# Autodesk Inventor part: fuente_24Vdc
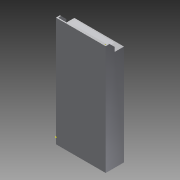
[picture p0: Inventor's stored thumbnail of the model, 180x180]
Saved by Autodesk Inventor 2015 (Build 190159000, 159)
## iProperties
Created: 2016-06
Part Number: fuente_24Vdc
Material: Genérico
Document SubType Name: Modeling
Designer: Diego
Density: 1 g/cm^3
Appearance: Valor por defecto
Author: Diego
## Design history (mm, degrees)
sketch "Boceto1"
  geometry: 1 further point
sketch "Boceto2"
  geometry: L1 (0, 0)-(95, 0); L2 (95, 0)-(95, 35); L3 (95, 35)-(0, 35); L4 (0, 35)-(0, 0)
  constraints: 8 end point, 2 parallel, 1 horizontal, 1 perpendicular
  dimensions: "d0" = 95 distance of L3.end L2.end; "d1" = 35 distance of L2.end L1.end
extrude "Extrusión1" new body sketch "Boceto2" distance "d2" = 180; taper "d3" = 0 deg
sketch "Boceto3"
  geometry: L1 (0, 35)-(0, 0) reference; L2 (0, 17.5)-(0, 0); L3 (0, 0)-(95, 0); L4 (95, 0)-(95, 17.5); L5 (95, 0)-(95, 35) reference; L6 (93, 17.5)-(93, 2); L7 (93, 2)-(2, 2); L8 (2, 2)-(2, 17.5); L9 (0, 17.5)-(2, 17.5); L10 (93, 17.5)-(95, 17.5)
  constraints: 16 end point, 2 collinear, 2 midpoint, 2 perpendicular, 1 horizontal, 2 other
  dimensions: "d4" = 2 distance between parallel lines of L3 L7
extrude "Extrusión2" join sketch "Boceto3" distance "d5" = 18; taper "d6" = 0 deg
chamfer "Chaflán1" distance "d7" = 10; stored, may be unused: second distance "d8" = 2, angle "d9" = 45 deg
chamfer "Chaflán2" distance "d10" = 10; stored, may be unused: second distance "d11" = 2, angle "d12" = 45 deg
sketch "Boceto4"
  geometry: L1 (93, 0)-(-2, 0) reference; L2 (2.896, 0)-(77.896, 0); L3 (77.896, 0)-(77.896, -10); L4 (77.896, -10)-(2.896, -10); L5 (2.896, -10)-(2.896, 0); 1 further point
  constraints: 8 end point, 2 parallel, 1 horizontal, 1 perpendicular, 1 point on line
  dimensions: "d13" = 75 distance of L3.end L4.end; "d14" = 10 distance of L2.end L3.end
extrude "Extrusión3" join sketch "Boceto4" distance "d15" = 1; taper "d16" = 0 deg
sketch "Boceto5" dims "d23" = 10
  geometry: L1 (77.896, -10)-(2.896, -10) reference; L2 (2.896, 0)-(4.396, 0); L3 (4.396, 0)-(4.396, -10); L4 (4.396, -10)-(2.896, -10); L5 (2.896, -10)-(2.896, 0); L6 (14.846, 0)-(14.846, -10); L7 (13.346, -10)-(13.346, 0); L8 (13.346, 0)-(14.846, 0); L9 (14.846, -10)-(13.346, -10); L10 (25.296, 0)-(25.296, -10); L11 (23.796, -10)-(23.796, 0); L12 (23.796, 0)-(25.296, 0); L13 (25.296, -10)-(23.796, -10); L14 (35.746, 0)-(35.746, -10); L15 (34.246, -10)-(34.246, 0); L16 (34.246, 0)-(35.746, 0); L17 (35.746, -10)-(34.246, -10); L18 (46.196, 0)-(46.196, -10); L19 (44.696, -10)-(44.696, 0); L20 (44.696, 0)-(46.196, 0); L21 (46.196, -10)-(44.696, -10); L22 (56.646, 0)-(56.646, -10); L23 (55.146, -10)-(55.146, 0); L24 (55.146, 0)-(56.646, 0); L25 (56.646, -10)-(55.146, -10); L26 (67.096, 0)-(67.096, -10); L27 (65.596, -10)-(65.596, 0); L28 (65.596, 0)-(67.096, 0); L29 (67.096, -10)-(65.596, -10); L30 (77.546, 0)-(77.546, -10); L31 (76.046, -10)-(76.046, 0); L32 (76.046, 0)-(77.546, 0); L33 (77.546, -10)-(76.046, -10); 1 further point
  constraints: 64 end point, 2 horizontal, 2 parallel, 1 perpendicular, 1 point on line, 56 other
  dimensions: "d17" = 1.5 distance of L3.end L4.end; "d20" = 10.45 distance of L2.end L6.start
extrude "Extrusión4" join sketch "Boceto5" distance "d25" = 10; taper "d26" = 0 deg
chamfer "Chaflán3" distance "d27" = 6; stored, may be unused: second distance "d28" = 2, angle "d29" = 45 deg
chamfer "Chaflán4" distance "d30" = 6; stored, may be unused: second distance "d31" = 2, angle "d32" = 45 deg
chamfer "Chaflán5" distance "d33" = 6; stored, may be unused: second distance "d34" = 2, angle "d35" = 45 deg
chamfer "Chaflán6" distance "d36" = 6; stored, may be unused: second distance "d37" = 2, angle "d38" = 45 deg
chamfer "Chaflán7" distance "d39" = 6; stored, may be unused: second distance "d40" = 2, angle "d41" = 45 deg
sketch "Boceto6"
  geometry: L1 (-95, 35)-(0, 35) reference; L2 (0, 0)-(-95, 0) reference; L3 (0, 35)-(0, 0) reference; L4 (-95, 35)-(0, 35) reference; L5 (-95, 0)-(-95, 35) reference; L6 (0, 35)-(-95, 35); L7 (-95, 35)-(-95, 0); L8 (-95, 0)-(0, 0); L9 (0, 0)-(0, 35); L10 (-2, 2)-(-93, 2); L11 (-93, 2)-(-93, 33); L12 (-93, 33)-(-2, 33); L13 (-2, 33)-(-2, 2); 1 further point
  constraints: 16 end point, 2 parallel, 1 horizontal, 1 perpendicular, 3 other
  dimensions: "d42" = 2 distance between parallel lines of L3 L13
extrude "Extrusión5" cut sketch "Boceto6" distance "d43" = 178; taper "d44" = 0 deg
sketch "Boceto7"
  geometry: L1 (5, -180)-(5, -175); L2 (5, -175)-(0, -175); 631 further points
  constraints: 4 end point, 1 coincident, 1 horizontal, 1 vertical, 629 other
  dimensions: "d45" = 5 distance of L2.end L1.end; "d46" = 5 distance of L1.end L1.start; "d49" = 5 distance of point (5, -175) point (5, -170); "d52" = 5 distance of point (5, -175) point (10, -175)
hole "Agujero1" sketch "Boceto7" diameter "d55" = 2; stored, may be unused: countersink angle "d59" = 90 deg, drill point angle "d61" = 118 deg; dims "d56" = 6, "d57" = 4, "d58" = 2, "d60" = 3
sketch "Boceto8"
  geometry: L1 (5, 0)-(5, 5); L2 (5, 5)-(0, 5); 210 further points
  constraints: 4 end point, 1 coincident, 1 horizontal, 1 vertical, 209 other
  dimensions: "d62" = 5 distance of L2.end L1.end; "d63" = 5 distance of L1.end L1.start; "d66" = 5 distance of L1.end point (5, 10); "d69" = 5 distance of L1.end point (10, 5)
hole "Agujero2" sketch "Boceto8" diameter "d72" = 2; stored, may be unused: countersink angle "d76" = 90 deg, drill point angle "d78" = 118 deg; dims "d73" = 6, "d74" = 4, "d75" = 2, "d77" = 3
sketch "Boceto9"
  geometry: L1 (0, 35)-(-95, 35); L2 (-95, 35)-(-95, 0); L3 (-95, 0)-(0, 0); L4 (0, 0)-(0, 35); 1 further point
  constraints: 8 end point, 2 parallel, 1 horizontal, 1 perpendicular
extrude "Extrusión6" join sketch "Boceto9" distance "d79" = 2; taper "d80" = 0 deg
sketch "Boceto10"
  geometry: L1 (0, 0)-(-95, 0); L2 (-95, 0)-(-95, 35); L3 (-95, 35)-(-93, 35); L4 (-95, 35)-(0, 35) reference; L5 (-93, 2)-(-93, 33) reference; L6 (-93, 35)-(-93, 2); L7 (-93, 2)-(0, 2); L8 (0, 7.5)-(0, 0) reference; L9 (0, 0)-(0, 2)
  constraints: 12 end point, 2 perpendicular, 2 point on line, 1 collinear, 1 horizontal
  dimensions: "d81" = 2 distance of L2.end L3.end
extrude "Extrusión7" join sketch "Boceto10" distance "d82" = 10; taper "d83" = 0 deg
sketch "Boceto11" dims "d89" = 10
  geometry: L1 (4.396, -10)-(13.346, -4); L2 (13.346, -4)-(13.346, -10); L3 (13.346, -10)-(13.346, 0) reference; L4 (13.346, -10)-(4.396, -4); L5 (6.246, -8.76)-(11.488, -8.76); L6 (11.488, -8.76)-(11.488, -5.246); L7 (11.488, -5.246)-(6.246, -5.246); L8 (6.246, -5.246)-(6.246, -8.76); L9 (16.696, -5.246)-(16.696, -8.76); L10 (16.696, -8.76)-(21.938, -8.76); L11 (21.938, -8.76)-(21.938, -5.246); L12 (21.938, -5.246)-(16.696, -5.246); L13 (27.146, -5.246)-(27.146, -8.76); L14 (27.146, -8.76)-(32.388, -8.76); L15 (32.388, -8.76)-(32.388, -5.246); L16 (32.388, -5.246)-(27.146, -5.246); L17 (37.596, -5.246)-(37.596, -8.76); L18 (37.596, -8.76)-(42.838, -8.76); L19 (42.838, -8.76)-(42.838, -5.246); L20 (42.838, -5.246)-(37.596, -5.246); L21 (48.046, -5.246)-(48.046, -8.76); L22 (48.046, -8.76)-(53.288, -8.76); L23 (53.288, -8.76)-(53.288, -5.246); L24 (53.288, -5.246)-(48.046, -5.246); L25 (58.496, -5.246)-(58.496, -8.76); L26 (58.496, -8.76)-(63.738, -8.76); L27 (63.738, -8.76)-(63.738, -5.246); L28 (63.738, -5.246)-(58.496, -5.246); L29 (68.946, -5.246)-(68.946, -8.76); L30 (68.946, -8.76)-(74.188, -8.76); L31 (74.188, -8.76)-(74.188, -5.246); L32 (74.188, -5.246)-(68.946, -5.246); 1 further point
  constraints: 62 end point, 2 collinear, 2 horizontal, 2 parallel, 2 point on line, 1 perpendicular, 47 other
  dimensions: "d86" = 10.45 distance of L7.end L9.start
extrude "Extrusión8" join sketch "Boceto11" distance "d91" = 1.5; taper "d92" = 0 deg
sketch "Boceto12" dims "d98" = 10
  geometry: L1 (6.246, -8.76)-(11.488, -5.246); L2 (11.488, -5.246)-(6.246, -5.246); L3 (6.246, -5.246)-(6.246, -8.76) reference; L4 (6.246, -5.246)-(11.488, -8.76); C1 r 1.426 at (8.867, -7.003); C2 r 1.426 at (19.317, -7.003); C3 r 1.426 at (29.767, -7.003); C4 r 1.426 at (40.217, -7.003); C5 r 1.426 at (50.667, -7.003); C6 r 1.426 at (61.117, -7.003); C7 r 1.426 at (71.567, -7.003); 1 further point
  constraints: 7 centre point, 6 end point, 1 horizontal, 1 midpoint, 1 perpendicular, 12 other
  dimensions: "d95" = 10.45 distance of C1.centre C2.centre
extrude "Extrusión9" join sketch "Boceto12" distance "d100" = 1.5; taper "d101" = 0 deg
fillet "Empalme1" dims "d102" = 1
sketch "Boceto13" dims "d108" = 10
  geometry: L1 (-0.871, -1.129)-(1.194, 0.781); L2 (1.194, 0.781)-(0.871, 1.129); L3 (-1.194, -0.781)-(0.871, 1.129); L4 (-1.194, -0.781)-(-0.871, -1.129); L5 (1.426, 0)-(0, 0); L6 (9.579, -1.129)-(11.644, 0.781); L7 (9.256, -0.781)-(9.579, -1.129); L8 (9.256, -0.781)-(11.321, 1.129); L9 (11.644, 0.781)-(11.321, 1.129); L10 (20.029, -1.129)-(22.094, 0.781); L11 (19.706, -0.781)-(20.029, -1.129); L12 (19.706, -0.781)-(21.771, 1.129); L13 (22.094, 0.781)-(21.771, 1.129); L14 (30.479, -1.129)-(32.544, 0.781); L15 (30.156, -0.781)-(30.479, -1.129); L16 (30.156, -0.781)-(32.221, 1.129); L17 (32.544, 0.781)-(32.221, 1.129); L18 (40.929, -1.129)-(42.994, 0.781); L19 (40.606, -0.781)-(40.929, -1.129); L20 (40.606, -0.781)-(42.671, 1.129); L21 (42.994, 0.781)-(42.671, 1.129); L22 (51.379, -1.129)-(53.444, 0.781); L23 (51.056, -0.781)-(51.379, -1.129); L24 (51.056, -0.781)-(53.121, 1.129); L25 (53.444, 0.781)-(53.121, 1.129); L26 (61.829, -1.129)-(63.894, 0.781); L27 (61.506, -0.781)-(61.829, -1.129); L28 (61.506, -0.781)-(63.571, 1.129); L29 (63.894, 0.781)-(63.571, 1.129); A1 r 1.426 centre (0, 0) between (-0.871, -1.129) and (1.194, 0.781) reference; 1 further point
  constraints: 58 end point, 5 point on circle, 3 perpendicular, 2 horizontal, 48 other
  dimensions: "d105" = 10.45 distance of L1.start L6.start
extrude "Extrusión10" cut sketch "Boceto13" distance "d110" = 0.5; taper "d111" = 0 deg
sketch "Boceto14"
  geometry: L1 (4.496, 22.479)-(79.496, 22.479); L2 (79.496, 22.479)-(79.496, 32.479); L3 (79.496, 32.479)-(4.496, 32.479); L4 (4.496, 32.479)-(4.496, 22.479); 1 further point
  constraints: 8 end point, 2 parallel, 1 horizontal, 1 perpendicular
  dimensions: "d112" = 75 distance of L3.end L2.end; "d113" = 10 distance of L2.end L1.end
extrude "Extrusión11" join sketch "Boceto14" distance "d114" = 0.0001; taper "d115" = 0 deg
sketch "Boceto15"
  geometry: L1 (77.896, -10)-(77.896, 0) reference; L2 (77.546, -10)-(77.896, -10); L3 (77.896, -10)-(77.896, -4); L4 (77.546, -4)-(77.546, -10); L5 (77.546, 0)-(77.896, 0); L6 (77.896, 0)-(77.896, -10); L7 (77.896, -10)-(77.546, -10); L8 (77.546, -10)-(77.546, 0); 1 further point
  constraints: 14 end point, 3 parallel, 2 horizontal, 2 perpendicular, 1 point on line
extrude "Extrusión12" cut sketch "Boceto15" distance "d116" = 1; taper "d117" = 0 deg
sketch "Boceto16"
  geometry: L1 (79.926, 8.507)-(84.926, 8.507); L2 (84.926, 8.507)-(84.926, 13.507); L3 (84.926, 13.507)-(79.926, 13.507); L4 (79.926, 13.507)-(79.926, 8.507); 1 further point
  constraints: 8 end point, 2 parallel, 1 horizontal, 1 perpendicular
  dimensions: "d118" = 5 distance of L3.end L2.end; "d119" = 5 distance of L2.end L1.end
extrude "Extrusión13" join sketch "Boceto16" distance "d120" = 3; taper "d121" = 0 deg
sketch "Boceto17"
  geometry: L1 (83.197, 12.133)-(83.197, 12.133); L2 (83.421, 10.005)-(81.339, 12.02); L3 (83.29, 9.87)-(81.207, 11.884); C1 r 1.5 at (82.335, 10.967); A1 r 1.45 centre (82.335, 10.967) between (83.421, 10.005) and (81.339, 12.02); A2 r 1.45 centre (82.335, 10.967) between (81.21, 11.881) and (83.287, 9.872); 1 further point
  constraints: 6 end point, 6 point on circle, 3 centre point, 2 point on line, 1 coincident, 1 parallel
  dimensions: "d122" = 3 diameter of C1
extrude "Extrusión14" cut sketch "Boceto17" distance "d124" = 2; taper "d125" = 0 deg
sketch "Boceto18"
  geometry: L1 (84.758, 6.774)-(87.696, 7.279); A1 r 2.5 centre (86.567, 5.049) between (84.758, 6.774) and (87.696, 7.279); 1 further point
  constraints: 2 end point, 2 point on circle, 1 centre point
  dimensions: "d126" = 5 diameter of A1
extrude "Extrusión15" join sketch "Boceto18" distance "d127" = 1.5; taper "d128" = 0 deg
sketch "Boceto19"
  geometry: L1 (84.88, 3.203)-(86.567, 5.049); C1 r 1.983 at (86.567, 5.049); A1 r 2.5 centre (86.567, 5.049) between (84.758, 6.774) and (87.696, 7.279) reference; 1 further point
  constraints: 2 end point, 1 centre point, 1 coincident, 1 point on circle
extrude "Extrusión16" join sketch "Boceto19" distance "d129" = 4; taper "d130" = 0 deg
fillet "Empalme2" dims "d131" = 1.8
node "Sólido1"
node "Contorno proyectado1"
other parameters: "d123" = 2.9
